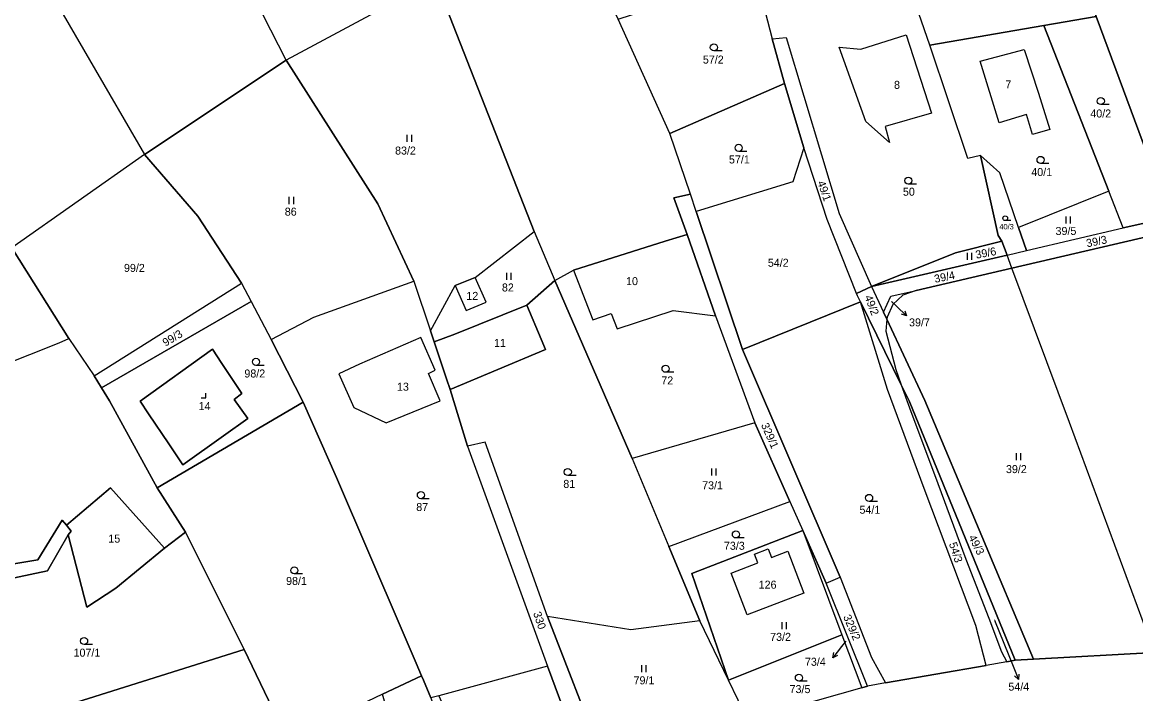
# Model space of a CAD drawing. Extents: x -590606 to -587796, y -1065936 to -1062515.
# Drawn here: x -588986.8 to -588750.2, y -1063914 to -1063771.4 of the extents above; entities that cross this region are included whole.
import ezdxf

# ---------------------------------------------------------------- set-up
doc = ezdxf.new("R2010")
doc.units = 0
for name, color, linetype in [('Parcela nároku', 7, 'Continuous'), ('Parcelní číslo', 7, 'Continuous'), ('Vrstva 30', 7, 'Continuous')]:
    doc.layers.add(name, color=color, linetype=linetype)

msp = doc.modelspace()

# ---------------------------------------------------------------- linework, layer by layer
at = {"layer": 'Parcela nároku'}
for points in [[(-588915.05, -1063719.98), (-588898.96, -1063762.41), (-588930.68, -1063779.51), (-588937.25, -1063766.73), (-588950.98, -1063737.57), (-588960.87, -1063714.33), (-588967.9, -1063700.67), (-588977.28, -1063682.45), (-588988.07, -1063656.88), (-588936.37, -1063667.89), (-588929.67, -1063686.07)], [(-589006.06, -1063715.24), (-588995.94, -1063739.11), (-588960.84, -1063799.54), (-588989.02, -1063819.29), (-588994.94, -1063811.86), (-589006.48, -1063793.6), (-589024.66, -1063772.58), (-589046.9, -1063728.25), (-589051.16, -1063720.8), (-589037.08, -1063705.89), (-589019.8, -1063682.85)], [(-588930.68, -1063779.51), (-588937.25, -1063766.73), (-588950.98, -1063737.57), (-588960.87, -1063714.33), (-588967.9, -1063700.67), (-589006.06, -1063715.24), (-588995.94, -1063739.11), (-588960.84, -1063799.54)], [(-588871.15, -1063728.75), (-588893.31, -1063721.6), (-588915.05, -1063719.98), (-588898.96, -1063762.41), (-588878.03, -1063815.85), (-588873.66, -1063826.25), (-588869.66, -1063824.08), (-588850.19, -1063817.93), (-588845.55, -1063816.47), (-588848.39, -1063808.69), (-588844.85, -1063807.93), (-588849.19, -1063795.07), (-588860.18, -1063770.74), (-588863.5, -1063763.51)], [(-589082.61, -1063758.61), (-589111.45, -1063786.24), (-589103.91, -1063795.61), (-589082.22, -1063823.01), (-589041.47, -1063862.89), (-589017.13, -1063854.66), (-588978.91, -1063839.48), (-588976.89, -1063838.59), (-588989.02, -1063819.29), (-588994.94, -1063811.86), (-589006.48, -1063793.6), (-589024.66, -1063772.58), (-589046.9, -1063728.25)], [(-588800.86, -1063752.46), (-588767.37, -1063743.88), (-588761.16, -1063762.69), (-588758.63, -1063770.24), (-588769.77, -1063772.13), (-588793.94, -1063776.29), (-588796.33, -1063769.6)], [(-588785.9, -1063800.35), (-588793.94, -1063776.29), (-588796.33, -1063769.6), (-588800.86, -1063752.46), (-588831.03, -1063761.24), (-588827.44, -1063774.96), (-588824.49, -1063774.65), (-588813.22, -1063812.04), (-588806.34, -1063827.54), (-588788.52, -1063820.38), (-588778.65, -1063817.94), (-588779.46, -1063816.73), (-588783.24, -1063799.73)], [(-588721.81, -1063775.15), (-588717.46, -1063785.01), (-588714.57, -1063790.47), (-588717.31, -1063791.84), (-588746.33, -1063803.42), (-588758.63, -1063770.24), (-588761.16, -1063762.69), (-588730.44, -1063753.9)], [(-588898.96, -1063762.41), (-588930.68, -1063779.51), (-588911.22, -1063809.98), (-588903.58, -1063826.39), (-588900.04, -1063836.93), (-588894.8, -1063827.31), (-588890.55, -1063825.59), (-588878.03, -1063815.85)], [(-588860.18, -1063770.74), (-588831.03, -1063761.24), (-588827.44, -1063774.96), (-588824.84, -1063784.42), (-588849.19, -1063795.07)], [(-588793.94, -1063776.29), (-588769.77, -1063772.13), (-588755.96, -1063807.29), (-588775.11, -1063814.98), (-588779.11, -1063803.39), (-588783.24, -1063799.73), (-588785.9, -1063800.35)], [(-588769.77, -1063772.13), (-588758.63, -1063770.24), (-588746.33, -1063803.42), (-588742.66, -1063812.78), (-588752.9, -1063815.09), (-588755.96, -1063807.29)], [(-588799.02, -1063774.13), (-588793.59, -1063790.76), (-588803.46, -1063793.59), (-588802.51, -1063796.96), (-588807.58, -1063792.53), (-588813.22, -1063776.73), (-588808.63, -1063777.13)], [(-588793.59, -1063790.76), (-588803.46, -1063793.59), (-588802.51, -1063796.96), (-588807.58, -1063792.53), (-588813.22, -1063776.73), (-588808.63, -1063777.13), (-588799.02, -1063774.13)], [(-588827.44, -1063774.96), (-588824.49, -1063774.65), (-588813.22, -1063812.04), (-588806.34, -1063827.54), (-588809.58, -1063829), (-588815.82, -1063813.29), (-588820.76, -1063798.06), (-588824.84, -1063784.42)], [(-588770.92, -1063786.52), (-588768.46, -1063794.2), (-588772.13, -1063795.27), (-588773.45, -1063791.04), (-588779.23, -1063792.75), (-588783.27, -1063779.67), (-588773.91, -1063777.2)], [(-588768.46, -1063794.2), (-588772.13, -1063795.27), (-588773.45, -1063791.04), (-588779.23, -1063792.75), (-588783.27, -1063779.67), (-588773.91, -1063777.2), (-588770.92, -1063786.52)], [(-588930.68, -1063779.51), (-588960.84, -1063799.54), (-588949.5, -1063812.6), (-588940.17, -1063826.84), (-588938.13, -1063830.74), (-588933.91, -1063838.81), (-588924.82, -1063834.02), (-588903.58, -1063826.39), (-588911.22, -1063809.98)], [(-588849.19, -1063795.07), (-588824.84, -1063784.42), (-588820.76, -1063798.06), (-588823.05, -1063805.29), (-588843.6, -1063811.64), (-588844.85, -1063807.93)], [(-588809.36, -1063829.48), (-588809.58, -1063829), (-588815.82, -1063813.29), (-588820.76, -1063798.06), (-588823.05, -1063805.29), (-588843.6, -1063811.64), (-588833.77, -1063840.88), (-588808.72, -1063830.77)], [(-588949.5, -1063812.6), (-588960.84, -1063799.54), (-588989.02, -1063819.29), (-588976.89, -1063838.59), (-588971.47, -1063846.51), (-588940.17, -1063826.84)], [(-588773.42, -1063819.86), (-588775.11, -1063814.98), (-588779.11, -1063803.39), (-588783.24, -1063799.73), (-588779.46, -1063816.73), (-588778.65, -1063817.94), (-588777.55, -1063820.87)], [(-588755.96, -1063807.29), (-588775.11, -1063814.98), (-588773.42, -1063819.86), (-588752.9, -1063815.09)], [(-588844.85, -1063807.93), (-588848.39, -1063808.69), (-588845.55, -1063816.47), (-588839.54, -1063833.73), (-588831.16, -1063856.47), (-588823.71, -1063873.18), (-588820.95, -1063879.37), (-588815.97, -1063890.53), (-588813.02, -1063889.28), (-588833.77, -1063840.88), (-588843.6, -1063811.64)], [(-588773.42, -1063819.86), (-588752.9, -1063815.09), (-588742.66, -1063812.78), (-588741.59, -1063815.53), (-588776.52, -1063823.63), (-588777.55, -1063820.87)], [(-588878.03, -1063815.85), (-588873.66, -1063826.25), (-588879.61, -1063831.52), (-588894.88, -1063837.67), (-588899.24, -1063839.3), (-588900.04, -1063836.93), (-588894.8, -1063827.31), (-588892.45, -1063832.64), (-588888.21, -1063830.86), (-588890.55, -1063825.59)], [(-588839.54, -1063833.73), (-588845.55, -1063816.47), (-588850.19, -1063817.93), (-588869.66, -1063824.08), (-588865.59, -1063834.59), (-588861.65, -1063833.28), (-588860.42, -1063836.54), (-588848.48, -1063832.64)], [(-588741.59, -1063815.53), (-588735.79, -1063830.19), (-588736.63, -1063830.45), (-588738.23, -1063825.25), (-588745.9, -1063827.63), (-588741.41, -1063842.09), (-588733.75, -1063839.71), (-588734.63, -1063836.89), (-588733.34, -1063836.48), (-588723.61, -1063861.83), (-588717.1, -1063879.86), (-588707.26, -1063907.1), (-588746.28, -1063905.22), (-588764.28, -1063856.39), (-588776.52, -1063823.63)], [(-588777.55, -1063820.87), (-588778.65, -1063817.94), (-588788.52, -1063820.38), (-588806.34, -1063827.54)], [(-588776.52, -1063823.63), (-588777.55, -1063820.87), (-588806.34, -1063827.54), (-588803.81, -1063833), (-588802.23, -1063829.6), (-588796.9, -1063828.36)], [(-588869.66, -1063824.08), (-588865.59, -1063834.59), (-588861.65, -1063833.28), (-588860.42, -1063836.54), (-588848.48, -1063832.64), (-588839.54, -1063833.73), (-588831.16, -1063856.47), (-588857.21, -1063864.02), (-588873.66, -1063826.25)], [(-588801.87, -1063831.35), (-588803.07, -1063834.01), (-588803.11, -1063834.5), (-588795.05, -1063851.73), (-588771.96, -1063906.67), (-588746.28, -1063905.22), (-588764.28, -1063856.39), (-588776.52, -1063823.63), (-588796.9, -1063828.36), (-588799.73, -1063829.38)], [(-588933.91, -1063838.81), (-588924.82, -1063834.02), (-588903.58, -1063826.39), (-588900.04, -1063836.93), (-588899.24, -1063839.3), (-588896.62, -1063847.13), (-588895.87, -1063849.37), (-588892.19, -1063861.45), (-588875.17, -1063908.15), (-588898.29, -1063914.41), (-588900.01, -1063914.87), (-588901.55, -1063911.13), (-588901.96, -1063910.16), (-588903.1, -1063907.49), (-588906.06, -1063900.55), (-588920, -1063868.06), (-588927.08, -1063852.06)], [(-588857.21, -1063864.02), (-588849.42, -1063882.7), (-588842.82, -1063898.51), (-588857.5, -1063900.46), (-588875.2, -1063897.61), (-588888.44, -1063860.6), (-588892.19, -1063861.45), (-588895.87, -1063849.37), (-588875.65, -1063840.93), (-588876.57, -1063838.75), (-588879.61, -1063831.52), (-588873.66, -1063826.25)], [(-588888.21, -1063830.86), (-588890.55, -1063825.59), (-588894.8, -1063827.31), (-588892.45, -1063832.64)], [(-588971.47, -1063846.51), (-588940.17, -1063826.84), (-588938.13, -1063830.74), (-588969.91, -1063849.07)], [(-588803.32, -1063837.05), (-588801.19, -1063845.17), (-588800.04, -1063848.44), (-588808.72, -1063830.77), (-588809.36, -1063829.48), (-588809.58, -1063829), (-588806.34, -1063827.54), (-588803.81, -1063833), (-588803.11, -1063834.5)], [(-588802.23, -1063829.6), (-588796.9, -1063828.36), (-588799.73, -1063829.38), (-588801.87, -1063831.35), (-588803.07, -1063834.01), (-588803.11, -1063834.5), (-588803.81, -1063833)], [(-588969.91, -1063849.07), (-588938.13, -1063830.74), (-588933.91, -1063838.81), (-588927.08, -1063852.06), (-588958.1, -1063870.25), (-588968.27, -1063851.78)], [(-588795.19, -1063870.4), (-588802.99, -1063849.41), (-588808.72, -1063830.77), (-588833.77, -1063840.88), (-588813.02, -1063889.28), (-588806.4, -1063906.3), (-588803.41, -1063911.69), (-588782.04, -1063907.97), (-588784.2, -1063899.54)], [(-588778.73, -1063905.12), (-588777.62, -1063907.21), (-588782.04, -1063907.97), (-588784.2, -1063899.54), (-588795.19, -1063870.4), (-588802.99, -1063849.41), (-588808.72, -1063830.77), (-588800.04, -1063848.44), (-588798.33, -1063853.28), (-588792.27, -1063869.36), (-588786.36, -1063885.45), (-588781.46, -1063897.93)], [(-588876.57, -1063838.75), (-588875.65, -1063840.93), (-588895.87, -1063849.37), (-588896.62, -1063847.13), (-588899.24, -1063839.3), (-588894.88, -1063837.67), (-588879.61, -1063831.52)], [(-588803.32, -1063837.05), (-588801.19, -1063845.17), (-588800.04, -1063848.44), (-588798.39, -1063851.79), (-588775.86, -1063906.9), (-588771.96, -1063906.67), (-588795.05, -1063851.73), (-588803.11, -1063834.5)], [(-588915.17, -1063844.01), (-588919.52, -1063846.04), (-588916.37, -1063853.24), (-588909.44, -1063856.51), (-588897.99, -1063851.81), (-588900.49, -1063845.99), (-588899.06, -1063845.31), (-588902.09, -1063838.36)], [(-588900.49, -1063845.99), (-588899.06, -1063845.31), (-588902.09, -1063838.36), (-588915.17, -1063844.01), (-588919.52, -1063846.04), (-588916.37, -1063853.24), (-588909.44, -1063856.51), (-588897.99, -1063851.81)], [(-588969.91, -1063849.07), (-588968.27, -1063851.78), (-588958.1, -1063870.25), (-588952.08, -1063879.66), (-588956.54, -1063883.07), (-588968.03, -1063870.31), (-588977.4, -1063878.2), (-588978.32, -1063877.14), (-588983.46, -1063885.54), (-589013.53, -1063890.56), (-589041.47, -1063862.89), (-589017.13, -1063854.66), (-588978.91, -1063839.48), (-588976.89, -1063838.59), (-588971.47, -1063846.51)], [(-588961.75, -1063851.9), (-588946.39, -1063840.87), (-588944.4, -1063843.85), (-588940.11, -1063850.26), (-588941.76, -1063851.49), (-588938.88, -1063855.59), (-588944, -1063859.23), (-588952.66, -1063865.39), (-588955.66, -1063860.95), (-588959.94, -1063854.59)], [(-588941.76, -1063851.49), (-588940.11, -1063850.26), (-588944.4, -1063843.85), (-588946.39, -1063840.87), (-588961.75, -1063851.9), (-588959.94, -1063854.59), (-588955.66, -1063860.95), (-588952.66, -1063865.39), (-588944, -1063859.23), (-588938.88, -1063855.59)], [(-588775.86, -1063906.9), (-588798.39, -1063851.79), (-588800.04, -1063848.44), (-588798.33, -1063853.28), (-588792.27, -1063869.36), (-588786.36, -1063885.45), (-588781.46, -1063897.93), (-588778.73, -1063905.12), (-588777.62, -1063907.21)], [(-588927.08, -1063852.06), (-588920, -1063868.06), (-588906.06, -1063900.55), (-588903.1, -1063907.49), (-588901.96, -1063910.16), (-588910.23, -1063914.1), (-588931.41, -1063924.18), (-588933.62, -1063917.1), (-588939.65, -1063904.58), (-588952.08, -1063879.66), (-588958.1, -1063870.25)], [(-588831.16, -1063856.47), (-588857.21, -1063864.02), (-588849.42, -1063882.7), (-588823.71, -1063873.18)], [(-588888.44, -1063860.6), (-588892.19, -1063861.45), (-588875.17, -1063908.15), (-588867.52, -1063928.72), (-588863.64, -1063927.3), (-588875.2, -1063897.61)], [(-588977.05, -1063880.26), (-588976.4, -1063879.47), (-588977.4, -1063878.2), (-588968.03, -1063870.31), (-588956.54, -1063883.07), (-588966.91, -1063891.55), (-588973.04, -1063895.63)], [(-588849.42, -1063882.7), (-588823.71, -1063873.18), (-588820.95, -1063879.37), (-588844.52, -1063888.5), (-588836.75, -1063911.14), (-588842.82, -1063898.51)], [(-589028.49, -1063889.47), (-589013.53, -1063890.56), (-588983.46, -1063885.54), (-588978.32, -1063877.14), (-588977.4, -1063878.2), (-588976.4, -1063879.47), (-588977.05, -1063880.26), (-588981.38, -1063887.88), (-589010.57, -1063894.09), (-589025.93, -1063892.96), (-589037.53, -1063890.69), (-589053.07, -1063887.41), (-589053.21, -1063884.95)], [(-589010.57, -1063894.09), (-588981.38, -1063887.88), (-588977.05, -1063880.26), (-588973.04, -1063895.63), (-588966.91, -1063891.55), (-588956.54, -1063883.07), (-588952.08, -1063879.66), (-588939.65, -1063904.58), (-588990.51, -1063920.59)], [(-588844.52, -1063888.5), (-588820.95, -1063879.37), (-588812.67, -1063901.49), (-588836.75, -1063911.14)], [(-588815.97, -1063890.53), (-588820.95, -1063879.37), (-588812.67, -1063901.49), (-588808.45, -1063912.75), (-588807.22, -1063912.4)], [(-588827.59, -1063885.1), (-588824.11, -1063883.76), (-588820.72, -1063892.65), (-588832.76, -1063897.25), (-588836.17, -1063888.4), (-588830.52, -1063886.23), (-588831.24, -1063884.35), (-588828.32, -1063883.22)], [(-588832.76, -1063897.25), (-588836.17, -1063888.4), (-588830.52, -1063886.23), (-588831.24, -1063884.35), (-588828.32, -1063883.22), (-588827.59, -1063885.1), (-588824.11, -1063883.76), (-588820.72, -1063892.65)], [(-588813.02, -1063889.28), (-588806.4, -1063906.3), (-588803.41, -1063911.69), (-588807.22, -1063912.4), (-588815.97, -1063890.53)], [(-588857.5, -1063900.46), (-588875.2, -1063897.61), (-588863.64, -1063927.3), (-588859.62, -1063926.3), (-588861.33, -1063919.41), (-588856.05, -1063918.43), (-588854.45, -1063925.02), (-588832.67, -1063919.62), (-588836.75, -1063911.14), (-588842.82, -1063898.51)], [(-588836.75, -1063911.14), (-588812.67, -1063901.49), (-588808.45, -1063912.75), (-588832.67, -1063919.62)], [(-588959.37, -1063964.26), (-588960.88, -1063964.65), (-588983.18, -1063930.34), (-588990.51, -1063920.59), (-588939.65, -1063904.58), (-588933.62, -1063917.1), (-588931.41, -1063924.18), (-588928, -1063935.09), (-588924.53, -1063943.8), (-588923.06, -1063947.48), (-588943.02, -1063959.97)], [(-588867.52, -1063928.72), (-588875.17, -1063908.15), (-588898.29, -1063914.41), (-588890.55, -1063931.96), (-588877.01, -1063931.48)], [(-588900.01, -1063914.87), (-588892.64, -1063935.89), (-588914.54, -1063944.45), (-588934.55, -1063957.54), (-588943.02, -1063959.97), (-588923.06, -1063947.48), (-588924.53, -1063943.8), (-588912.46, -1063939.33), (-588908.48, -1063937.2), (-588907.21, -1063939.64), (-588901.57, -1063936.62), (-588902.78, -1063934.15), (-588902.19, -1063933.84), (-588899.04, -1063932.15), (-588903.62, -1063923.81), (-588906.77, -1063925.45), (-588907.2, -1063924.66), (-588910.23, -1063914.1), (-588901.96, -1063910.16), (-588901.55, -1063911.13)]]:
    msp.add_lwpolyline(points, close=True, dxfattribs=at)
msp.add_lwpolyline([(-588746.28, -1063905.22), (-588771.96, -1063906.67), (-588775.86, -1063906.9), (-588777.62, -1063907.21), (-588782.04, -1063907.97), (-588803.41, -1063911.69), (-588807.22, -1063912.4), (-588808.45, -1063912.75), (-588832.67, -1063919.62)], dxfattribs=at)
at = {"layer": 'Parcelní číslo'}
for p, q in [((-588802.11, -1063830.7), (-588801.09, -1063831.69)), ((-588801.09, -1063831.69), (-588798.94, -1063833.78)), ((-588780.22, -1063898.39), (-588776.26, -1063908.16)), ((-588812.76, -1063903.99), (-588814.59, -1063906.36)), ((-588811.84, -1063902.8), (-588812.76, -1063903.99)), ((-588776.26, -1063908.16), (-588775.13, -1063910.94))]:
    msp.add_line(p, q, dxfattribs=at)
for points in [[(-588799.31, -1063832.72), (-588798.94, -1063833.78), (-588800, -1063833.44)], [(-588813.59, -1063905.88), (-588814.59, -1063906.36), (-588814.38, -1063905.27)], [(-588775.04, -1063909.83), (-588775.13, -1063910.94), (-588775.97, -1063910.2)]]:
    msp.add_lwpolyline(points, dxfattribs=at)
at = {"layer": 'Vrstva 30'}
for p, q in [((-588838.11, -1063777.52), (-588839.86, -1063777.52)), ((-588755.9, -1063788.91), (-588757.65, -1063788.91)), ((-588905.06, -1063795.34), (-588905.06, -1063796.84)), ((-588904.04, -1063796.84), (-588904.04, -1063795.34)), ((-588832.83, -1063798.84), (-588834.58, -1063798.84)), ((-588768.7, -1063801.4), (-588770.45, -1063801.4)), ((-588796.8, -1063805.81), (-588798.55, -1063805.81)), ((-588930.13, -1063808.52), (-588930.13, -1063810.02)), ((-588929.1, -1063810.02), (-588929.1, -1063808.52)), ((-588776.79, -1063813.54), (-588777.96, -1063813.54)), ((-588765.09, -1063812.64), (-588765.09, -1063814.14)), ((-588764.07, -1063814.14), (-588764.07, -1063812.64)), ((-588786.04, -1063820.37), (-588786.04, -1063821.87)), ((-588785.02, -1063821.87), (-588785.02, -1063820.37)), ((-588883.92, -1063824.62), (-588883.92, -1063826.12)), ((-588882.9, -1063826.12), (-588882.9, -1063824.62)), ((-588935.38, -1063844.28), (-588937.13, -1063844.28)), ((-588848.37, -1063845.75), (-588850.12, -1063845.75)), ((-588775.65, -1063862.9), (-588775.65, -1063864.4)), ((-588774.62, -1063864.4), (-588774.62, -1063862.9)), ((-588840.37, -1063866.17), (-588840.37, -1063867.67)), ((-588839.34, -1063867.67), (-588839.34, -1063866.17)), ((-588869.13, -1063867.67), (-588870.88, -1063867.67)), ((-588900.34, -1063872.58), (-588902.09, -1063872.58)), ((-588805.12, -1063873.16), (-588806.87, -1063873.16)), ((-588833.42, -1063880.92), (-588835.17, -1063880.92)), ((-588927.24, -1063888.56), (-588928.99, -1063888.56)), ((-588825.43, -1063898.81), (-588825.43, -1063900.31)), ((-588824.41, -1063900.31), (-588824.41, -1063898.81)), ((-588971.89, -1063903.55), (-588973.64, -1063903.55)), ((-588855.24, -1063907.92), (-588855.24, -1063909.42)), ((-588854.21, -1063909.42), (-588854.21, -1063907.92)), ((-588820.04, -1063911.35), (-588821.79, -1063911.35))]:
    msp.add_line(p, q, dxfattribs=at)
msp.add_lwpolyline([(-588948.77, -1063851.15), (-588947.77, -1063851.15), (-588947.77, -1063850.15)], dxfattribs=at)
for centre, radius in [((-588839.86, -1063776.77), 0.75), ((-588757.65, -1063788.16), 0.75), ((-588834.58, -1063798.09), 0.75), ((-588770.45, -1063800.65), 0.75), ((-588798.55, -1063805.06), 0.75), ((-588777.96, -1063813.04), 0.503), ((-588937.13, -1063843.53), 0.75), ((-588850.12, -1063845), 0.75), ((-588870.88, -1063866.92), 0.75), ((-588902.09, -1063871.83), 0.75), ((-588806.87, -1063872.41), 0.75), ((-588835.17, -1063880.17), 0.75), ((-588928.99, -1063887.81), 0.75), ((-588973.64, -1063902.8), 0.75), ((-588821.79, -1063910.6), 0.75)]:
    msp.add_circle(centre, radius, dxfattribs=at)

# ---------------------------------------------------------------- texts
at = {"layer": 'Parcela nároku'}
for s, height, p in [('57/2', 1.7, (-588842.19, -1063780.2)), ('8', 1.7, (-588801.58, -1063785.57)), ('7', 1.7, (-588777.93, -1063785.47)), ('40/2', 1.7, (-588759.88, -1063791.65)), ('83/2', 1.7, (-588907.58, -1063799.52)), ('57/1', 1.7, (-588836.65, -1063801.41)), ('40/1', 1.7, (-588772.42, -1063804.08)), ('50', 1.7, (-588799.69, -1063808.26)), ('86', 1.7, (-588931.01, -1063812.49)), ('40/3', 1.14, (-588779.21, -1063815.41)), ('39/5', 1.7, (-588767.27, -1063816.59)), ('54/2', 1.7, (-588828.39, -1063823.34)), ('99/2', 1.7, (-588965.17, -1063824.44)), ('10', 1.7, (-588858.51, -1063827.24)), ('12', 1.7, (-588892.44, -1063830.38)), ('82', 1.7, (-588884.88, -1063828.59)), ('39/7', 0.1, (-588802.11, -1063830.7)), ('11', 1.7, (-588886.55, -1063840.35)), ('98/2', 1.7, (-588939.59, -1063846.85)), ('72', 1.7, (-588851.02, -1063848.32)), ('13', 1.7, (-588907.17, -1063849.66)), ('14', 1.7, (-588949.32, -1063853.77)), ('39/2', 1.7, (-588777.8, -1063867.15)), ('81', 1.7, (-588871.84, -1063870.29)), ('73/1', 1.7, (-588842.35, -1063870.59)), ('87', 1.7, (-588903.08, -1063875.2)), ('54/1', 1.7, (-588808.92, -1063875.78)), ('15', 1.7, (-588968.49, -1063881.91)), ('73/3', 1.7, (-588837.72, -1063883.43)), ('98/1', 1.7, (-588930.73, -1063890.9)), ('126', 1.7, (-588830.34, -1063891.69)), ('54/4', 0.1, (-588780.41, -1063898.37)), ('73/2', 1.7, (-588827.9, -1063902.77)), ('107/1', 1.7, (-588975.88, -1063906.12)), ('73/4', 0.1, (-588811.98, -1063902.8)), ('79/1', 1.7, (-588856.91, -1063912)), ('73/5', 1.7, (-588823.77, -1063913.86))]:
    msp.add_text(s, height=height, dxfattribs=at).set_placement(p)
for s, rotation, p in [('49/1', 289.5159, (-588817.91, -1063805.43)), ('39/3', 11.3828, (-588760.56, -1063819.22)), ('39/6', 10.7519, (-588784.1, -1063821.65)), ('39/4', 11.3222, (-588792.86, -1063826.77)), ('49/2', 291.0426, (-588807.89, -1063829.73)), ('99/3', 30.7025, (-588956.35, -1063840.33)), ('329/1', 293.8993, (-588829.88, -1063856.93)), ('49/3', 297, (-588785.81, -1063880.79)), ('54/3', 288, (-588789.94, -1063882.13)), ('330', 288.435, (-588878.26, -1063896.89)), ('329/2', 293.2418, (-588812.42, -1063897.64))]:
    msp.add_text(s, height=1.7, rotation=rotation, dxfattribs=at).set_placement(p)
at = {"layer": 'Parcelní číslo'}
for s, p in [('39/7', (-588798.39, -1063836)), ('73/4', (-588820.51, -1063908.06)), ('54/4', (-588777.29, -1063913.34))]:
    msp.add_text(s, height=1.7, dxfattribs=at).set_placement(p)

doc.saveas('drawing.dxf')
